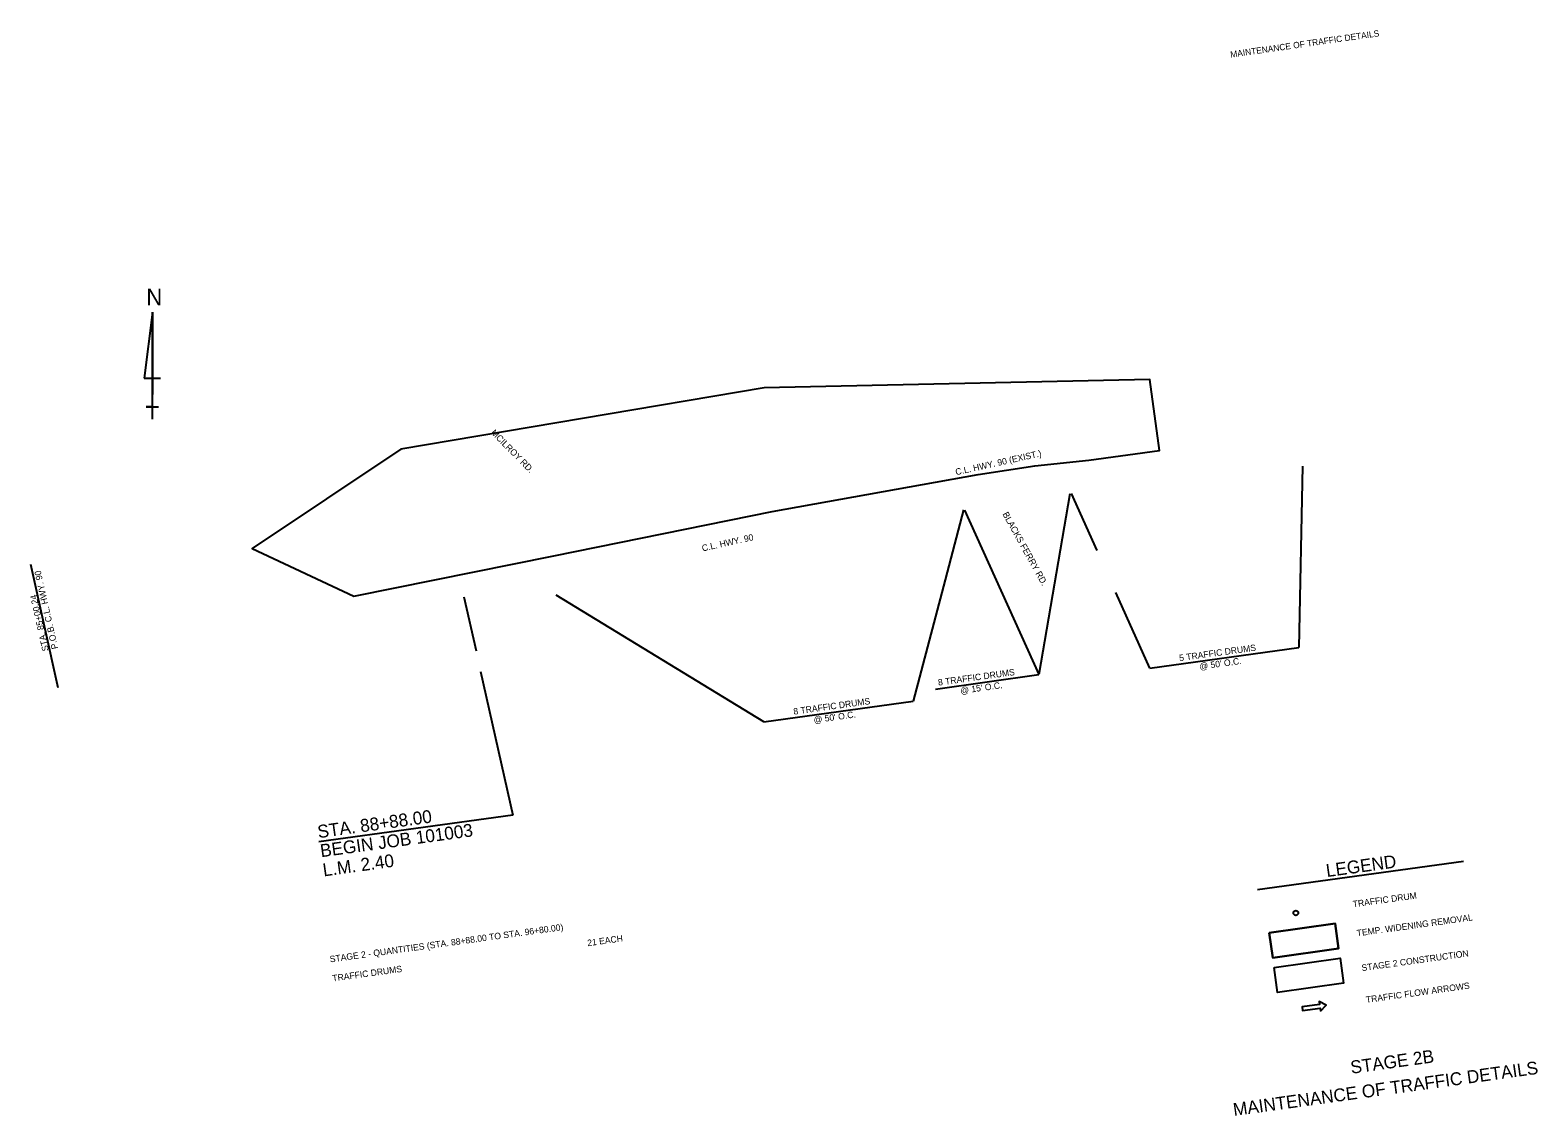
# Model space of a CAD drawing. Extents: x 1568785 to 1570191, y 731522 to 732535.
import ezdxf

# ---------------------------------------------------------------- set-up
doc = ezdxf.new("R2010")
doc.units = 0
for name, color, linetype in [('Level 47', 7, 'Continuous'), ('R_Annotation', 7, 'Continuous'), ('R_Border', 7, 'Continuous'), ('R_Horz Alg Annot', 7, 'Continuous'), ('R_MOT', 7, 'Continuous'), ('R_No Plot', 7, 'Continuous'), ('R_Proposed Road_Lane', 7, 'Continuous')]:
    doc.layers.add(name, color=color, linetype=linetype)

msp = doc.modelspace()

# ---------------------------------------------------------------- linework, layer by layer
at = {"layer": 'Level 47'}
msp.add_circle((1569965.4, 731711.6), 2.25, dxfattribs=at)
at = {"layer": 'R_Annotation'}
for p, q in [((1569971.5, 732128.3), (1569968.3, 731959.2)), ((1569754.7, 732102.6), (1569725.6, 731933.9)), ((1569779.9, 732049.6), (1569756, 732102.8)), ((1569655.4, 732087.8), (1569636.6, 732016.6)), ((1569656.4, 732087.3), (1569725.6, 731933.9)), ((1569636.6, 732016.6), (1569608.4, 731909.3)), ((1569189.3, 732006.4), (1569200.6, 731956)), ((1569469.1, 731889.9), (1569275.5, 732008)), ((1569829.1, 731939.8), (1569797.4, 732010.4)), ((1569829.1, 731939.8), (1569968.3, 731959.2)), ((1569204.9, 731936.9), (1569234.9, 731802.9)), ((1569629.2, 731920.4), (1569725.6, 731933.9)), ((1569469.1, 731889.9), (1569608.4, 731909.3)), ((1569234.9, 731802.9), (1569054.1, 731777.8)), ((1569929.7, 731733.4), (1570121.8, 731760))]:
    msp.add_line(p, q, dxfattribs=at)
at = {"layer": 'R_Horz Alg Annot'}
msp.add_line((1568810.9, 731921.7), (1568785.2, 732036.8), dxfattribs=at)
at = {"layer": 'R_MOT'}
for p, q in [((1570002.1, 731701.6), (1569940.6, 731693.1)), ((1569940.6, 731693.1), (1569943.8, 731669.8)), ((1569940.6, 731693.1), (1569943.8, 731669.8))]:
    msp.add_line(p, q, dxfattribs=at)
for points in [[(1569940.6, 731693.1), (1570002.1, 731701.6), (1570005.3, 731678.4), (1569943.8, 731669.8)], [(1569940.6, 731693.1), (1570002.1, 731701.6), (1570005.3, 731678.4), (1569943.8, 731669.8)], [(1569945.1, 731660.8), (1570006.6, 731669.3), (1570009.8, 731646), (1569948.3, 731637.5)], [(1569945.1, 731660.8), (1570006.6, 731669.3), (1570009.8, 731646), (1569948.3, 731637.5)], [(1569988.4, 731620.1), (1569993.6, 731625.4), (1569987.2, 731629), (1569987.6, 731626.2), (1569971.2, 731623.9), (1569971.6, 731620.6), (1569988, 731622.9)]]:
    msp.add_lwpolyline(points, close=True, dxfattribs=at)
for points in [[(1569943.8, 731669.8), (1570005.3, 731678.4), (1570002.1, 731701.6), (1569940.6, 731693.1)], [(1569943.8, 731669.8), (1570005.3, 731678.4), (1570002.1, 731701.6)]]:
    msp.add_lwpolyline(points, dxfattribs=at)
at = {"layer": 'R_No Plot'}
msp.add_lwpolyline([(1569086.7, 732007.1), (1569273.3, 732044.9), (1569476.9, 732086.2), (1569669, 732120.5), (1569721.8, 732128.6), (1569772.2, 732134.1), (1569838.3, 732143), (1569829.3, 732209.1), (1569469.5, 732201.5), (1569130.4, 732144.2), (1568991.8, 732051.7)], close=True, dxfattribs=at)
at = {"layer": 'R_Proposed Road_Lane'}
for p, q in [((1568898.7, 732272.1), (1568891, 732210.6)), ((1568898.7, 732172.1), (1568898.7, 732272.1)), ((1568898.7, 732272.1), (1568898.7, 732195.2)), ((1568891, 732210.6), (1568906.4, 732210.6)), ((1568898.7, 732183.7), (1568892.9, 732183.7)), ((1568892.9, 732183.7), (1568904.4, 732183.7)), ((1568898.7, 732172.1), (1568898.7, 732195.2)), ((1568898.7, 732172.1), (1568898.7, 732183.7))]:
    msp.add_line(p, q, dxfattribs=at)

# ---------------------------------------------------------------- texts
at = {"layer": 'R_Annotation'}
for s, height, p in [('5 TRAFFIC DRUMS', 6, (1569857, 731946.4)), ("@ 50' O.C. ", 6, (1569875.9, 731938.5)), ('8 TRAFFIC DRUMS', 6, (1569632, 731923.6)), ("@ 15' O.C. ", 6, (1569652.8, 731915.9)), ('8 TRAFFIC DRUMS', 6, (1569497.1, 731896.5)), ("@ 50' O.C. ", 6, (1569516, 731888.6)), ('STA. 88+88.00', 12, (1569053.6, 731781.3)), ('BEGIN JOB 101003', 12, (1569056.1, 731763.5)), ('L.M. 2.40', 12, (1569058.5, 731745.6)), ('LEGEND', 12, (1569994.4, 731745)), ('TRAFFIC DRUM', 6, (1570018.9, 731716.8)), ('TEMP. WIDENING REMOVAL', 6, (1570022.6, 731689.7)), ('STAGE 2 - QUANTITIES (STA. 88+88.00 TO STA. 96+80.00)', 6, (1569064.6, 731665.4)), ('21 EACH ', 6, (1569304.8, 731680.5)), ('STAGE 2 CONSTRUCTION', 6, (1570027.1, 731657.3)), ('TRAFFIC DRUMS ', 6, (1569067, 731647.6)), ('TRAFFIC FLOW ARROWS', 6, (1570031.2, 731627.6)), ('STAGE 2B', 12, (1570017.2, 731561.5)), ('MAINTENANCE OF TRAFFIC DETAILS', 12, (1569907.7, 731522.1))]:
    msp.add_text(s, height=height, rotation=7.8929, dxfattribs=at).set_placement(p)
at = {"layer": 'R_Border'}
msp.add_text('MAINTENANCE OF TRAFFIC DETAILS', height=5.862, rotation=8.1989, dxfattribs=at).set_placement((1569904.7, 732509.5))
at = {"layer": 'R_Horz Alg Annot'}
for s, rotation, p in [('MCILROY RD.', 314.5601, (1569214, 732159.1)), ('C.L. HWY. 90 (EXIST.)', 12.4985, (1569648.5, 732119.9)), ('BLACKS FERRY RD.', 299.0375, (1569691.5, 732083.7)), ('C.L. HWY. 90', 12.4985, (1569412, 732048.8)), ('P.O.B. C.L. HWY. 90', 102.6177, (1568810.8, 731958.4)), ('STA. 85+00.24', 102.6177, (1568802.1, 731956.5))]:
    msp.add_text(s, height=6, rotation=rotation, dxfattribs=at).set_placement(p)
at = {"layer": 'R_Proposed Road_Lane'}
msp.add_text('N', height=15.4, dxfattribs=at).set_placement((1568893, 732278.5))

doc.saveas('drawing.dxf')
